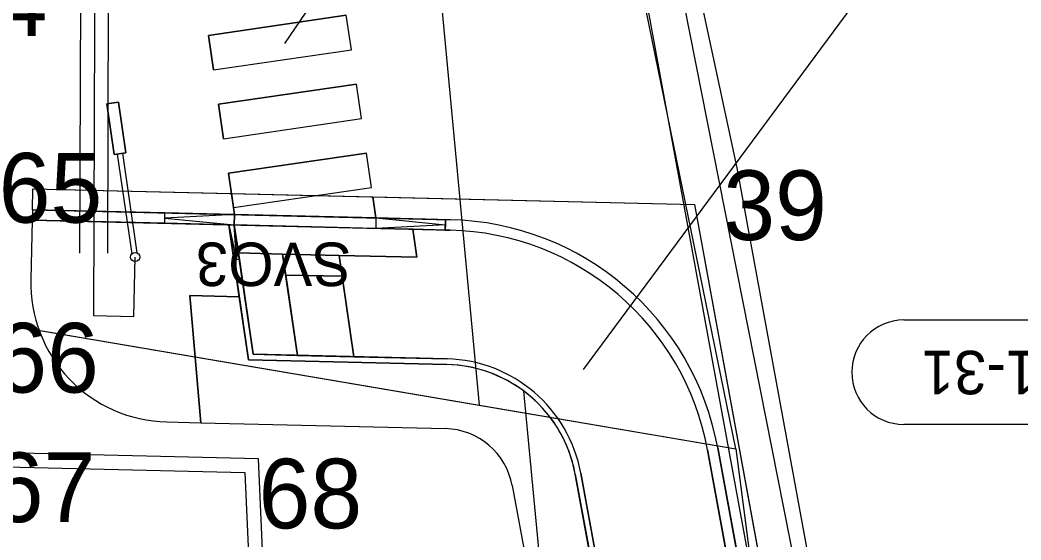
# Model space of a CAD drawing. Extents: x -728800 to -728100, y -1073200 to -1072700.
# Drawn here: x -728520.98 to -728506.62, y -1073033.85 to -1073026.38 of the extents above; entities that cross this region are included whole.
import ezdxf

# ---------------------------------------------------------------- set-up
doc = ezdxf.new("R2010")
doc.units = 0
for name, color, linetype in [('_NOR-návrh tenká', 7, 'Continuous'), ('_NOR-návrh tenká obec', 7, 'Continuous'), ('_NOR-VDZ', 7, 'Continuous'), ('_NOR-šraf_+12', 7, 'Continuous'), ('_NOR-šraf_+6', 7, 'Continuous'), ('_NOR-šraf_bezbariéra', 7, 'Continuous'), ('_NOR-šraf_chodník', 7, 'Continuous'), ('_NOR-šraf_signální pás', 7, 'Continuous'), ('_NOR-šraf_varovný pás', 7, 'Continuous'), ('_NOR-šraf_vozovka', 7, 'Continuous'), ('_NOR-šraf_zeleň', 7, 'Continuous'), ('A1_OBVOD Spravy železnic', 7, 'Continuous'), ('A2_OBVOD STAVBY', 7, 'Continuous'), ('B1_body_poloha', 7, 'Continuous'), ('B2_body_číslo', 7, 'Continuous'), ('K_01_Hranice parcel', 7, 'Continuous'), ('KOS_kabelová trasa VO', 7, 'Continuous'), ('KOS_nové prvky VO', 7, 'Continuous'), ('KTA_členění PS a SO', 7, 'Continuous'), ('ZA_02_Dočasný_do_1_roku', 7, 'Continuous')]:
    doc.layers.add(name, color=color, linetype=linetype)

msp = doc.modelspace()

# ---------------------------------------------------------------- linework, layer by layer
at = {"layer": '_NOR-návrh tenká'}
for p, q in [((-728520.806, -1073029.105), (-728520.81, -1073029.255)), ((-728518.907, -1073029.3), (-728518.904, -1073029.151)), ((-728517.904, -1073029.174), (-728518.905, -1073029.225)), ((-728518.905, -1073029.225), (-728517.908, -1073029.324)), ((-728517.904, -1073029.174), (-728517.908, -1073029.324)), ((-728515.876, -1073029.222), (-728515.879, -1073029.372)), ((-728515.876, -1073029.222), (-728514.878, -1073029.321)), ((-728514.88, -1073029.396), (-728514.876, -1073029.246)), ((-728517.989, -1073029.322), (-728517.875, -1073029.825)), ((-728517.875, -1073029.825), (-728517.908, -1073029.324)), ((-728514.878, -1073029.321), (-728515.879, -1073029.372)), ((-728515.347, -1073029.385), (-728515.288, -1073029.787)), ((-728517.835, -1073029.819), (-728517.914, -1073029.831)), ((-728517.002, -1073031.196), (-728517.215, -1073029.741)), ((-728516.191, -1073031.215), (-728516.404, -1073029.76))]:
    msp.add_line(p, q, dxfattribs=at)
for points in [[(-728520.806, -1073029.105), (-728520.799, -1073028.805), (-728511.304, -1073029.031), (-728510.067, -1073035.777)], [(-728520.806, -1073029.105), (-728514.808, -1073029.248)], [(-728520.81, -1073029.255), (-728514.811, -1073029.398)], [(-728514.857, -1073031.327), (-728517.706, -1073031.26), (-728517.989, -1073029.322)], [(-728514.855, -1073031.247), (-728517.636, -1073031.181), (-728517.908, -1073029.324)], [(-728517.849, -1073029.726), (-728515.288, -1073029.787)], [(-728511.116, -1073032.553), (-728510.51, -1073035.858)], [(-728510.968, -1073032.525), (-728510.362, -1073035.831)], [(-728512.663, -1073034.374), (-728512.935, -1073032.886)], [(-728512.741, -1073034.388), (-728513.014, -1073032.9)]]:
    msp.add_lwpolyline(points, dxfattribs=at)
for radius in [4, 3.85, 2, 1.92]:
    msp.add_arc((-728514.903, -1073033.247), radius, 10.3872, 88.6393, dxfattribs=at)
at = {"layer": '_NOR-návrh tenká obec'}
for p, q in [((-728518.28, -1073026.601), (-728516.301, -1073026.312)), ((-728516.228, -1073026.807), (-728516.301, -1073026.312)), ((-728518.207, -1073027.096), (-728518.28, -1073026.601)), ((-728518.207, -1073027.096), (-728516.228, -1073026.807)), ((-728518.135, -1073027.59), (-728516.156, -1073027.301)), ((-728516.084, -1073027.796), (-728516.156, -1073027.301)), ((-728518.063, -1073028.085), (-728518.135, -1073027.59)), ((-728518.063, -1073028.085), (-728516.084, -1073027.796)), ((-728517.991, -1073028.58), (-728516.012, -1073028.291)), ((-728515.939, -1073028.786), (-728516.012, -1073028.291)), ((-728517.919, -1073029.075), (-728517.991, -1073028.58)), ((-728517.919, -1073029.075), (-728515.939, -1073028.786))]:
    msp.add_line(p, q, dxfattribs=at)
at = {"layer": '_NOR-VDZ'}
for p, q in [((-728518.28, -1073026.601), (-728516.301, -1073026.312)), ((-728516.228, -1073026.807), (-728516.301, -1073026.312)), ((-728518.207, -1073027.096), (-728518.28, -1073026.601)), ((-728518.207, -1073027.096), (-728516.228, -1073026.807)), ((-728518.135, -1073027.59), (-728516.156, -1073027.301)), ((-728516.084, -1073027.796), (-728516.156, -1073027.301)), ((-728518.063, -1073028.085), (-728518.135, -1073027.59)), ((-728518.063, -1073028.085), (-728516.084, -1073027.796)), ((-728517.991, -1073028.58), (-728516.012, -1073028.291)), ((-728515.939, -1073028.786), (-728516.012, -1073028.291)), ((-728517.919, -1073029.075), (-728517.991, -1073028.58)), ((-728517.919, -1073029.075), (-728515.939, -1073028.786))]:
    msp.add_line(p, q, dxfattribs=at)
for points in [[(-728512.949, -1073020.89), (-728510.942, -1073031.839)], [(-728518.207, -1073027.096), (-728516.228, -1073026.807), (-728516.301, -1073026.312), (-728518.28, -1073026.601), (-728518.207, -1073027.096), (-728518.207, -1073027.096)], [(-728518.063, -1073028.085), (-728516.084, -1073027.796), (-728516.156, -1073027.301), (-728518.135, -1073027.59), (-728518.063, -1073028.085), (-728518.063, -1073028.085)], [(-728517.919, -1073029.075), (-728515.939, -1073028.786), (-728516.012, -1073028.291), (-728517.991, -1073028.58), (-728517.919, -1073029.075), (-728517.919, -1073029.075)], [(-728510.942, -1073031.839), (-728510.215, -1073035.804)]]:
    msp.add_lwpolyline(points, dxfattribs=at)
at = {"layer": '_NOR-šraf_+12'}
for p, q in [((-728514.876, -1073029.246), (-728514.878, -1073029.321)), ((-728514.808, -1073029.248), (-728514.876, -1073029.246)), ((-728514.878, -1073029.321), (-728514.88, -1073029.396)), ((-728514.88, -1073029.396), (-728514.811, -1073029.398)), ((-728511.116, -1073032.553), (-728510.51, -1073035.858)), ((-728510.362, -1073035.831), (-728510.968, -1073032.525))]:
    msp.add_line(p, q, dxfattribs=at)
msp.add_lwpolyline([(-728520.81, -1073029.255), (-728518.907, -1073029.3), (-728518.905, -1073029.225), (-728518.904, -1073029.151), (-728520.806, -1073029.105), (-728520.81, -1073029.255)], dxfattribs=at)
for radius in [4, 3.85]:
    msp.add_arc((-728514.903, -1073033.247), radius, 10.3872, 88.6393, dxfattribs=at)
at = {"layer": '_NOR-šraf_+6'}
for p, q in [((-728517.875, -1073029.825), (-728517.989, -1073029.322)), ((-728517.989, -1073029.322), (-728517.706, -1073031.26)), ((-728517.908, -1073029.324), (-728517.875, -1073029.825)), ((-728517.849, -1073029.726), (-728517.908, -1073029.324)), ((-728517.835, -1073029.819), (-728517.849, -1073029.726)), ((-728517.636, -1073031.181), (-728517.835, -1073029.819)), ((-728517.706, -1073031.26), (-728514.857, -1073031.327)), ((-728517.002, -1073031.196), (-728517.636, -1073031.181)), ((-728516.191, -1073031.215), (-728517.002, -1073031.196)), ((-728514.855, -1073031.247), (-728516.191, -1073031.215)), ((-728512.707, -1073034.135), (-728512.935, -1073032.886)), ((-728513.014, -1073032.9), (-728512.788, -1073034.135))]:
    msp.add_line(p, q, dxfattribs=at)
for radius in [2, 1.92]:
    msp.add_arc((-728514.903, -1073033.247), radius, 10.3872, 88.6393, dxfattribs=at)
at = {"layer": '_NOR-šraf_bezbariéra'}
msp.add_lwpolyline([(-728517.904, -1073029.174), (-728515.876, -1073029.222), (-728515.879, -1073029.372), (-728517.908, -1073029.324), (-728517.904, -1073029.174), (-728517.904, -1073029.174)], dxfattribs=at)
at = {"layer": '_NOR-šraf_chodník'}
for p, q in [((-728510.51, -1073035.858), (-728511.116, -1073032.553)), ((-728512.935, -1073032.886), (-728512.663, -1073034.374))]:
    msp.add_line(p, q, dxfattribs=at)
for points in [[(-728514.811, -1073029.398), (-728514.88, -1073029.396), (-728515.347, -1073029.385), (-728515.288, -1073029.787)], [(-728517.636, -1073031.181), (-728517.002, -1073031.196), (-728517.215, -1073029.741), (-728517.849, -1073029.726), (-728517.835, -1073029.819), (-728517.636, -1073031.181)], [(-728515.288, -1073029.787), (-728516.404, -1073029.76), (-728516.191, -1073031.215), (-728514.855, -1073031.247)]]:
    msp.add_lwpolyline(points, dxfattribs=at)
for radius in [3.85, 2]:
    msp.add_arc((-728514.903, -1073033.247), radius, 10.3872, 88.6393, dxfattribs=at)
at = {"layer": '_NOR-šraf_signální pás'}
for p, q in [((-728516.36, -1073030.061), (-728517.171, -1073030.042)), ((-728517.171, -1073030.042), (-728517.002, -1073031.196)), ((-728516.191, -1073031.215), (-728516.36, -1073030.061)), ((-728517.002, -1073031.196), (-728516.191, -1073031.215))]:
    msp.add_line(p, q, dxfattribs=at)
msp.add_lwpolyline([(-728516.36, -1073030.061), (-728516.404, -1073029.76), (-728517.215, -1073029.741), (-728517.171, -1073030.042), (-728516.36, -1073030.061)], dxfattribs=at)
at = {"layer": '_NOR-šraf_varovný pás'}
msp.add_lwpolyline([(-728517.849, -1073029.726), (-728517.215, -1073029.741), (-728516.404, -1073029.76), (-728515.288, -1073029.787), (-728515.347, -1073029.385), (-728515.879, -1073029.372), (-728517.908, -1073029.324), (-728517.849, -1073029.726)], dxfattribs=at)
at = {"layer": '_NOR-šraf_vozovka'}
for p, q in [((-728515.876, -1073029.222), (-728515.92, -1073028.921)), ((-728515.92, -1073028.921), (-728511.304, -1073029.031)), ((-728515.92, -1073028.921), (-728515.876, -1073029.222)), ((-728511.304, -1073029.031), (-728510.067, -1073035.777)), ((-728514.808, -1073029.248), (-728515.876, -1073029.222)), ((-728510.362, -1073035.831), (-728510.968, -1073032.525))]:
    msp.add_line(p, q, dxfattribs=at)
for points in [[(-728517.948, -1073028.873), (-728517.904, -1073029.174), (-728518.904, -1073029.151), (-728520.806, -1073029.105), (-728520.799, -1073028.805), (-728517.948, -1073028.873)], [(-728515.876, -1073029.222), (-728517.904, -1073029.174), (-728517.948, -1073028.873), (-728515.92, -1073028.921)]]:
    msp.add_lwpolyline(points, dxfattribs=at)
msp.add_arc((-728514.903, -1073033.247), 4, 10.3872, 88.6393, dxfattribs=at)
at = {"layer": '_NOR-šraf_zeleň'}
for p, q in [((-728517.838, -1073030.354), (-728518.545, -1073030.338)), ((-728518.545, -1073030.338), (-728518.39, -1073032.164)), ((-728517.706, -1073031.26), (-728517.838, -1073030.354)), ((-728514.857, -1073031.327), (-728517.706, -1073031.26)), ((-728513.489, -1073034.507), (-728513.751, -1073031.711)), ((-728513.489, -1073034.507), (-728513.751, -1073031.711)), ((-728518.39, -1073032.164), (-728514.879, -1073032.247)), ((-728513.014, -1073032.9), (-728512.788, -1073034.135)), ((-728513.919, -1073033.066), (-728513.447, -1073035.644))]:
    msp.add_line(p, q, dxfattribs=at)
msp.add_lwpolyline([(-728518.878, -1073032.152), (-728518.39, -1073032.164), (-728518.545, -1073030.338), (-728517.838, -1073030.354), (-728517.989, -1073029.322), (-728518.907, -1073029.3), (-728520.81, -1073029.255), (-728520.83, -1073030.105), (-728520.83, -1073030.105)], dxfattribs=at)
for centre, radius, start, end in [((-728518.83, -1073030.153), 2, 178.6393, 268.6393), ((-728514.903, -1073033.247), 1.92, 53.1299, 88.6393), ((-728514.903, -1073033.247), 1.92, 10.3872, 53.1299), ((-728514.903, -1073033.247), 1, 10.3872, 88.6393)]:
    msp.add_arc(centre, radius, start, end, dxfattribs=at)
at = {"layer": 'A1_OBVOD Spravy železnic'}
msp.add_lwpolyline([(-728604.14, -1072988.92), (-728582.13, -1073004.22), (-728556.03, -1073020.59), (-728543.86, -1073026.9), (-728510.71, -1073032.54), (-728510.22, -1073036.28), (-728509.42, -1073042.19), (-728509.9, -1073046.86), (-728541.12, -1073039.22), (-728572.55, -1073027.78), (-728581.66, -1073022.5), (-728594.83, -1073014.86), (-728598.74, -1073012.6)], dxfattribs=at)
at = {"layer": 'A2_OBVOD STAVBY'}
for points in [[(-728509.455, -1073035.234), (-728510.689, -1073028.502), (-728511.933, -1073022.707), (-728511.986, -1073020.002), (-728513.157, -1073020.217), (-728515.255, -1073019.379), (-728517.216, -1073018.59), (-728517.096, -1073019.442), (-728517.727, -1073020.685), (-728519.2, -1073021.56), (-728519.78, -1073021.597), (-728522.531, -1073023.408), (-728531.159, -1073023.437), (-728533.997, -1073023.341), (-728538.386, -1073022.967), (-728542.291, -1073022.287), (-728547.296, -1073020.586), (-728553.966, -1073017.86)], [(-728556.425, -1073019.431), (-728548.14, -1073022.833), (-728542.882, -1073024.621), (-728538.694, -1073025.349), (-728534.14, -1073025.737), (-728532.664, -1073025.787), (-728522.232, -1073025.806), (-728521.488, -1073028.32), (-728521.545, -1073030.726), (-728521.594, -1073032.788), (-728517.755, -1073032.879), (-728517.209, -1073045.129)]]:
    msp.add_lwpolyline(points, dxfattribs=at)
at = {"layer": 'B1_body_poloha'}
for p, q in [((-728510.89, -1073028.54), (-728510.89, -1073028.54)), ((-728517.56, -1073032.68), (-728517.56, -1073032.68))]:
    msp.add_line(p, q, dxfattribs=at)
at = {"layer": 'K_01_Hranice parcel'}
for p, q in [((-728510.71, -1073032.54), (-728513.08, -1073020.94)), ((-728514.39, -1073031.91), (-728515.38, -1073021.39)), ((-728514.39, -1073031.91), (-728510.71, -1073032.54))]:
    msp.add_line(p, q, dxfattribs=at)
for points in [[(-728564.68, -1073020.02), (-728543.86, -1073026.9), (-728514.39, -1073031.91)], [(-728510.71, -1073032.54), (-728510.22, -1073036.28), (-728501.19, -1073037.94)]]:
    msp.add_lwpolyline(points, dxfattribs=at)
at = {"layer": 'KOS_kabelová trasa VO'}
for p, q in [((-728520.126, -1073029.729), (-728520.105, -1073024.204)), ((-728519.726, -1073029.73), (-728519.705, -1073024.205))]:
    msp.add_line(p, q, dxfattribs=at)
msp.add_lwpolyline([(-728519.905, -1073023.659), (-728519.931, -1073030.624), (-728519.35, -1073030.638), (-728519.331, -1073029.784)], dxfattribs=at)
at = {"layer": 'KOS_nové prvky VO'}
for p, q in [((-728519.301, -1073029.725), (-728519.51, -1073028.295)), ((-728519.376, -1073029.736), (-728519.585, -1073028.306))]:
    msp.add_line(p, q, dxfattribs=at)
msp.add_lwpolyline([(-728519.632, -1073028.312), (-728519.738, -1073027.584), (-728519.57, -1073027.56), (-728519.463, -1073028.288)], close=True, dxfattribs=at)
msp.add_lwpolyline([(-728519.463, -1073028.288), (-728519.57, -1073027.56), (-728519.738, -1073027.584), (-728519.632, -1073028.312), (-728519.463, -1073028.288)], dxfattribs=at)
msp.add_circle((-728519.331, -1073029.784), 0.0665, dxfattribs=at)
at = {"layer": 'KTA_členění PS a SO'}
for p, q in [((-728509.672, -1073015.622), (-728517.188, -1073026.72)), ((-728507.548, -1073024.158), (-728512.902, -1073031.401))]:
    msp.add_line(p, q, dxfattribs=at)
for points in [[(-728508.3, -1073030.688), (-728503.3, -1073030.688)], [(-728503.3, -1073032.188), (-728508.3, -1073032.188)]]:
    msp.add_lwpolyline(points, dxfattribs=at)
msp.add_arc((-728508.295, -1073031.438), 0.75, 90.4529, 269.5471, dxfattribs=at)
at = {"layer": 'ZA_02_Dočasný_do_1_roku'}
msp.add_lwpolyline([(-728531.162, -1073023.637), (-728526.817, -1073023.623), (-728522.471, -1073023.608), (-728519.714, -1073021.793), (-728519.139, -1073021.757), (-728517.575, -1073020.827), (-728516.889, -1073019.476), (-728516.969, -1073018.905), (-728513.177, -1073020.424), (-728512.181, -1073020.241), (-728512.132, -1073022.73), (-728509.606, -1073035.517), (-728510.327, -1073035.465), (-728509.415, -1073042.185), (-728509.9, -1073046.86), (-728517.01, -1073045.12), (-728517.286, -1073038.902), (-728517.563, -1073032.683), (-728521.389, -1073032.592), (-728521.287, -1073028.294), (-728522.083, -1073025.607), (-728532.66, -1073025.587)], dxfattribs=at)

# ---------------------------------------------------------------- texts
at = {"layer": 'B2_body_číslo'}
for s, p in [('64', (-728522.08, -1073026.61)), ('65', (-728521.29, -1073029.29)), ('39', (-728510.89, -1073029.54)), ('66', (-728521.34, -1073031.73)), ('67', (-728521.39, -1073033.59)), ('68', (-728517.56, -1073033.68))]:
    msp.add_text(s, height=1, dxfattribs=at).set_placement(p)
at = {"layer": 'KOS_nové prvky VO'}
msp.add_text('SVO3', height=0.625, rotation=180, dxfattribs=at).set_placement((-728516.23, -1073029.576))
at = {"layer": 'KTA_členění PS a SO'}
msp.add_text('PS 11-01-31', height=0.625, rotation=180, dxfattribs=at).set_placement((-728503.35, -1073031.13))

doc.saveas('drawing.dxf')
